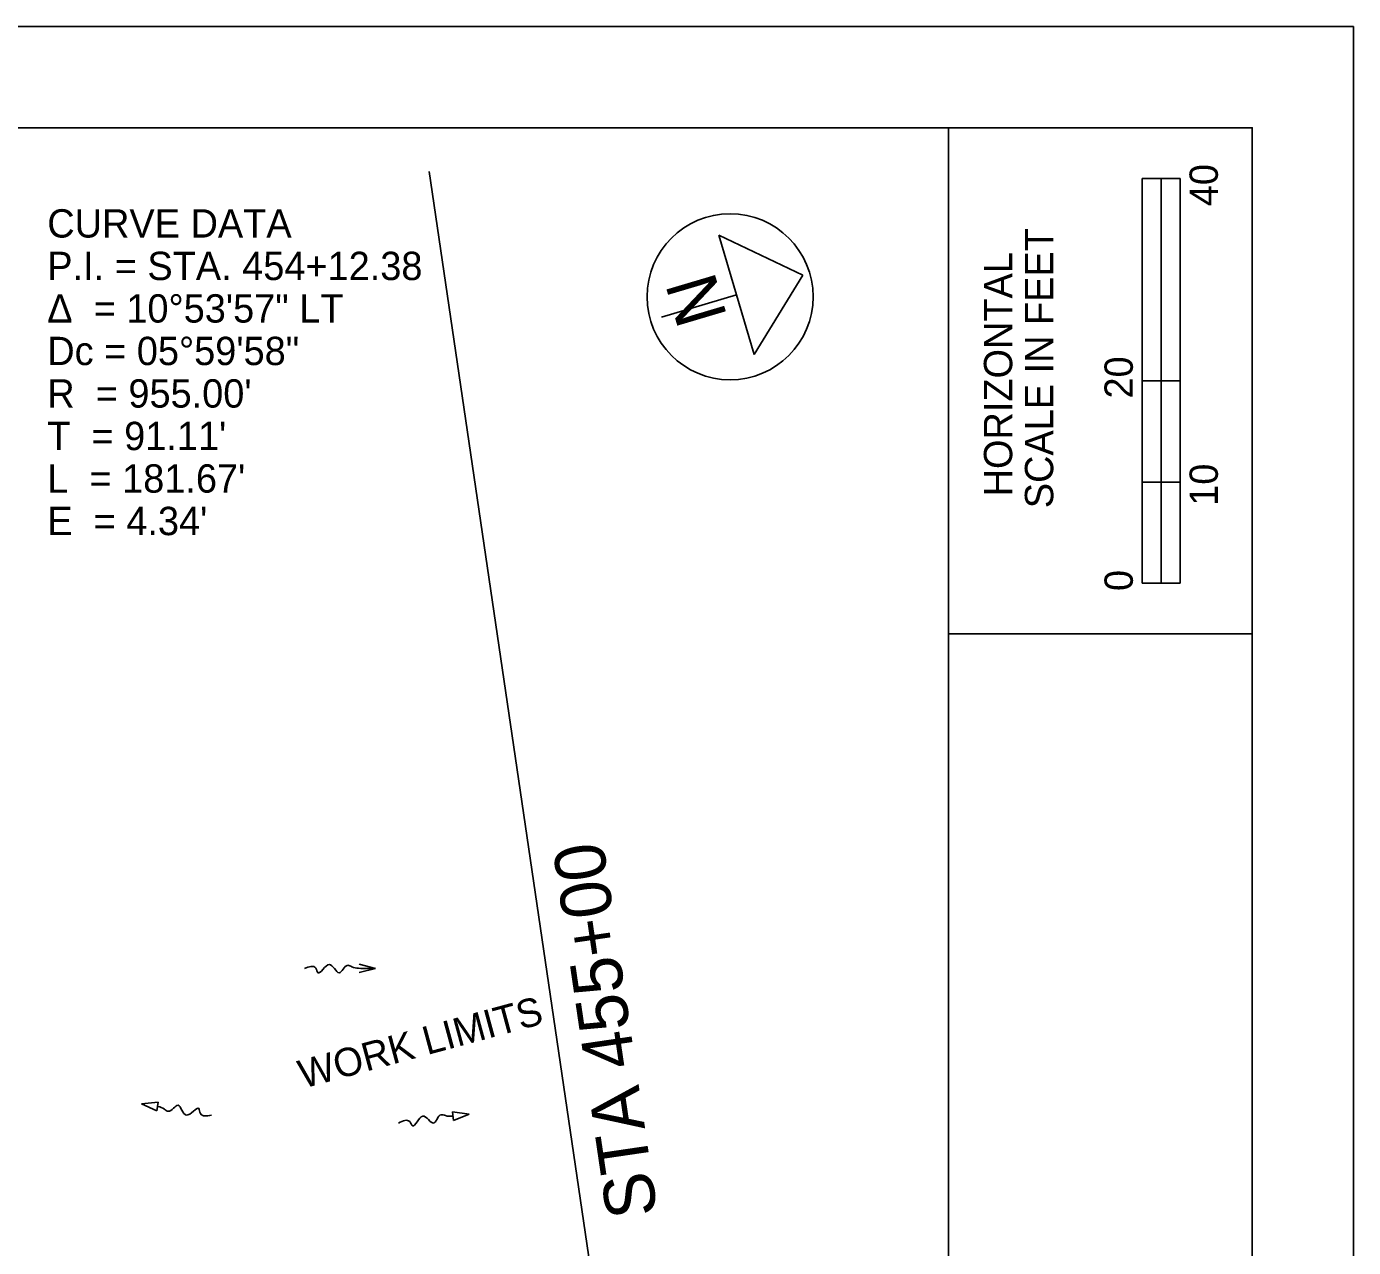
# Model space of a CAD drawing. Extents: x 0 to 3369, y -440 to 440.
# Drawn here: x 549 to 680, y 319.4 to 440 of the extents above; entities that cross this region are included whole.
import ezdxf

# ---------------------------------------------------------------- set-up
doc = ezdxf.new("R2010")
doc.units = 0
for name, color, linetype in [('DR_P_Culvert', 7, 'Continuous'), ('DR_X_Culvert', 7, 'Continuous'), ('MT_P_Edge_Line', 7, 'Continuous'), ('MT_P_Work_Area', 7, 'Continuous'), ('PF_X_Ground_Line', 7, 'Continuous'), ('PV_P_EOP', 7, 'Continuous'), ('PV_P_Shoulder', 7, 'Continuous'), ('SC_Scratch1', 7, 'Continuous'), ('TX_P_1', 7, 'Continuous')]:
    doc.layers.add(name, color=color, linetype=linetype)

msp = doc.modelspace()

# ---------------------------------------------------------------- linework, layer by layer
at = {"layer": 'DR_P_Culvert'}
for p, q in [((625.61, 415.43), (617.32, 419.39)), ((617.32, 419.39), (620.82, 407.59)), ((620.82, 407.59), (625.61, 415.43)), ((619.07, 413.49), (611.65, 411.29))]:
    msp.add_line(p, q, dxfattribs=at)
msp.add_circle((618.44, 413.3), 8.2, dxfattribs=at)
at = {"layer": 'DR_X_Culvert'}
for p, q in [((659.13, 385), (659.13, 425)), ((662.88, 425), (659.13, 425)), ((659.13, 405), (659.13, 425)), ((659.13, 425), (661, 425)), ((661, 425), (661.02, 425)), ((661.02, 425), (661.02, 405)), ((662.88, 425), (662.88, 385)), ((661.02, 405), (659.13, 405)), ((662.87, 405), (661, 405)), ((661, 405), (661, 395)), ((662.87, 395), (662.87, 405)), ((661, 395), (659.13, 395)), ((659.13, 395), (659.13, 385)), ((661, 385), (661, 395)), ((661, 395), (662.87, 395)), ((662.88, 385), (659.13, 385)), ((659.13, 385), (661, 385))]:
    msp.add_line(p, q, dxfattribs=at)
at = {"layer": 'MT_P_Edge_Line'}
msp.add_circle((618.44, 413.3), 8.2, dxfattribs=at)
at = {"layer": 'MT_P_Work_Area'}
for p, q in [((583.41, 346.95), (581.81, 347.38)), ((581.81, 346.53), (583.41, 346.95))]:
    msp.add_line(p, q, dxfattribs=at)
msp.add_spline([(583.41, 346.95), (581.75, 346.96), (581.09, 347.11), (580.67, 347.25), (579.82, 346.52), (578.85, 347.34), (577.73, 346.52), (577.51, 346.97), (576.41, 346.95)], degree=3, dxfattribs=at)
at = {"layer": 'PF_X_Ground_Line'}
for p, q in [((640, 10), (640, 430)), ((640, 380), (670, 380))]:
    msp.add_line(p, q, dxfattribs=at)
msp.add_lwpolyline([(30, 430), (670, 430), (670, 10), (30, 10)], close=True, dxfattribs=at)
at = {"layer": 'PV_P_EOP'}
msp.add_line((616.61, 235.96), (588.72, 425.67), dxfattribs=at)
at = {"layer": 'PV_P_Shoulder'}
for p, q in [((560.3, 333.57), (561.95, 333.73)), ((561.81, 332.89), (560.3, 333.57)), ((561.95, 333.73), (561.81, 332.89)), ((591.01, 332.77), (592.65, 332.54)), ((591.11, 331.91), (591.01, 332.77)), ((592.65, 332.54), (591.11, 331.91))]:
    msp.add_line(p, q, dxfattribs=at)
for points in [[(561.88, 333.31), (561.94, 333.3), (562.56, 333.04), (562.95, 332.83), (563.91, 333.42), (564.73, 332.45), (565.97, 333.09), (566.12, 332.61), (567.21, 332.44)], [(591.06, 332.34), (591, 332.34), (590.33, 332.4), (589.89, 332.49), (589.15, 331.66), (588.08, 332.36), (587.07, 331.4), (586.79, 331.81), (585.7, 331.66)]]:
    msp.add_spline(points, degree=3, dxfattribs=at)
at = {"layer": 'SC_Scratch1'}
msp.add_lwpolyline([(0, 0), (680, 0), (680, 440), (0, 440)], close=True, dxfattribs=at)

# ---------------------------------------------------------------- texts
at = {"layer": 'DR_P_Culvert'}
msp.add_text('N', height=5, rotation=286.5485, dxfattribs=at).set_placement((612, 414.55))
at = {"layer": 'DR_X_Culvert'}
for s, height, rotation, p in [('40', 2.8, 90, (666.61, 422.25)), ('SCALE IN FEET', 2.8, 90, (650.35, 392.41)), ('HORIZONTAL', 2.8, 90, (646.3, 393.58)), ('20', 2.8, 90, (658.21, 403.25)), ('10', 2.8, 90, (666.61, 392.65)), ('0', 2.8, 90, (658.21, 384.23)), ('MATCH LINE    STA 455+00', 5, 98.3657, (618.26, 275.26))]:
    msp.add_text(s, height=height, rotation=rotation, dxfattribs=at).set_placement(p)
at = {"layer": 'PV_P_EOP'}
msp.add_text('WORK LIMITS', height=2.8, rotation=15.1516, dxfattribs=at).set_placement((576.26, 335.06))
at = {"layer": 'TX_P_1'}
for s, p in [('CURVE DATA', (551, 419.15)), ('P.I. = STA. 454+12.38', (551, 414.95)), ('Δ  = 10°53\'57" LT', (551, 410.75)), ('Dc = 05°59\'58"', (551, 406.55)), ("R  = 955.00'", (551, 402.35)), ("T  = 91.11'", (551, 398.15)), ("L  = 181.67'", (551, 393.95)), ("E  = 4.34'", (551, 389.75))]:
    msp.add_text(s, height=2.8, dxfattribs=at).set_placement(p)

doc.saveas('drawing.dxf')
